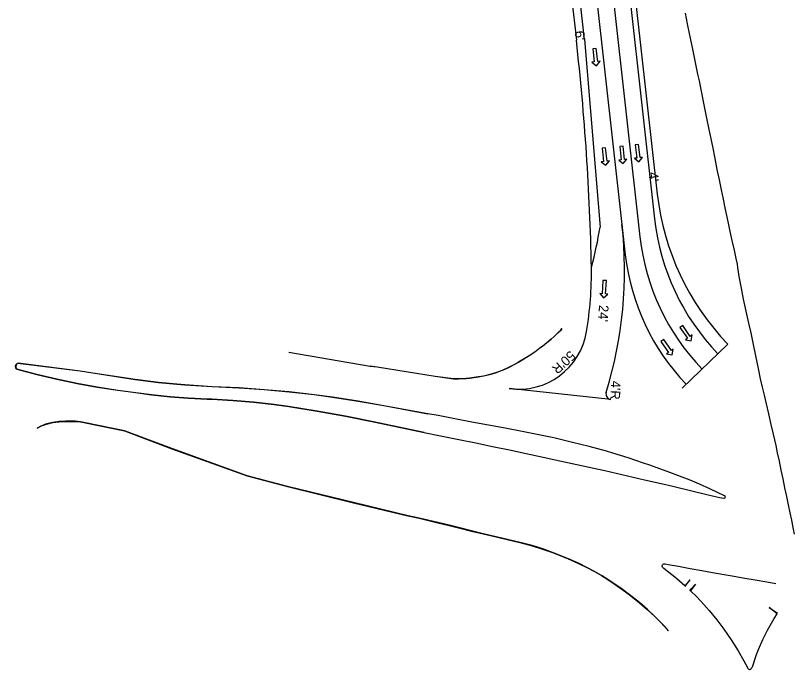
# Model space of a CAD drawing. Extents: x -5665 to 1997148, y 4 to 812485.
# Drawn here: x 1965954 to 1966519, y 789596 to 790071 of the extents above; entities that cross this region are included whole.
import ezdxf

# ---------------------------------------------------------------- set-up
doc = ezdxf.new("R2010")
doc.units = 0
for name, color, linetype in [('RD_EX_Conc', 7, 'Continuous'), ('RD_EX_Road', 7, 'Continuous'), ('RD_PD_ALT1_TrvlWay', 7, 'Continuous'), ('RD_PD_Final_LnLine', 7, 'Continuous'), ('RD_PD_PaveShd', 7, 'Continuous'), ('RD_SHT_TX', 7, 'Continuous')]:
    doc.layers.add(name, color=color, linetype=linetype)

msp = doc.modelspace()

# ---------------------------------------------------------------- linework, layer by layer
at = {"layer": 'RD_EX_Conc'}
msp.add_line((1966152.04, 789826.6), (1966211.27, 789816.49), dxfattribs=at)
for points in [[(1966335.83, 789830.34), (1966340.6, 789834.36), (1966342.72, 789836.11), (1966344.88, 789838.04), (1966348.33, 789841.41), (1966349.66, 789842.67), (1966350.56, 789843.7), (1966349.69, 789842.6), (1966344.95, 789837.97), (1966342.79, 789836.03), (1966336.32, 789830.73), (1966335.83, 789830.34), (1966330.76, 789826.57), (1966326.87, 789823.99), (1966324.42, 789822.5), (1966319, 789819.2), (1966317.35, 789818.26), (1966312.13, 789815.52), (1966307.89, 789813.61), (1966303.01, 789811.75), (1966299.07, 789810.56), (1966293.66, 789809.24), (1966289.86, 789808.56), (1966283.5, 789807.66), (1966280.9, 789807.4), (1966275.5, 789807.12), (1966271.82, 789807.15), (1966258.37, 789809), (1966216.2, 789815.73), (1966211.27, 789816.49), (1966216.21, 789815.83), (1966258.38, 789809.09), (1966271.83, 789807.25), (1966275.5, 789807.22), (1966280.89, 789807.5), (1966283.49, 789807.76), (1966289.84, 789808.65), (1966293.63, 789809.34), (1966299.04, 789810.65), (1966302.97, 789811.85), (1966307.85, 789813.7), (1966312.09, 789815.61), (1966317.3, 789818.35), (1966318.95, 789819.29), (1966326.8, 789824.07), (1966331.91, 789827.43)], [(1966250.48, 789768.18), (1966218.22, 789774.97), (1966213.64, 789775.94), (1966193.16, 789780.04), (1966172.6, 789783.74), (1966151.98, 789787.06), (1966141.38, 789788.49), (1966126.36, 789790.17), (1966111.3, 789791.46), (1966096.22, 789792.36), (1966092.74, 789792.46), (1966079.25, 789793.1), (1966065.78, 789794.13), (1966052.35, 789795.56), (1966038.97, 789797.38), (1966027.74, 789798.85), (1966012.92, 789801.15), (1965998.17, 789803.83), (1965983.49, 789806.9), (1965968.9, 789810.36), (1965954.39, 789814.21), (1965954.21, 789814.38), (1965953.67, 789815.25), (1965953.51, 789816.27), (1965953.76, 789817.28), (1965954.37, 789818.11), (1965955.27, 789818.64), (1966000.56, 789812.96), (1966009.7, 789811.49), (1966040.39, 789806.79), (1966044.33, 789806.22), (1966057.48, 789804.59), (1966070.68, 789803.34), (1966076.62, 789802.87), (1966096.36, 789801.57), (1966116.13, 789800.67), (1966134.17, 789799.44), (1966152.4, 789797.79), (1966170.58, 789795.76), (1966183.89, 789793.94), (1966202.51, 789791.06), (1966221.08, 789787.78), (1966253.16, 789781.91), (1966221.06, 789787.68), (1966202.5, 789790.96), (1966183.87, 789793.84), (1966170.57, 789795.66), (1966152.39, 789797.69), (1966134.16, 789799.34), (1966116.13, 789800.57), (1966096.36, 789801.47), (1966076.61, 789802.77), (1966070.67, 789803.24), (1966057.47, 789804.49), (1966044.31, 789806.13), (1966040.38, 789806.69), (1966009.68, 789811.39), (1966000.54, 789812.86), (1965955.29, 789818.54), (1965954.44, 789818.03), (1965953.85, 789817.23), (1965953.62, 789816.27), (1965953.77, 789815.29), (1965954.29, 789814.44), (1965954.44, 789814.3), (1965968.93, 789810.46), (1965983.52, 789807), (1965998.19, 789803.93), (1966012.94, 789801.24), (1966027.76, 789798.95), (1966038.98, 789797.47), (1966052.36, 789795.66), (1966065.79, 789794.23), (1966079.25, 789793.2), (1966092.74, 789792.56), (1966096.22, 789792.46), (1966111.31, 789791.56), (1966126.37, 789790.27), (1966141.39, 789788.59), (1966152, 789787.16), (1966172.62, 789783.84), (1966193.18, 789780.13), (1966213.66, 789776.04), (1966218.24, 789775.07), (1966250.48, 789768.21), (1966262.3, 789765.84), (1966275.71, 789763.17), (1966287.98, 789760.65), (1966300.19, 789758.08), (1966312.44, 789755.6), (1966324.68, 789752.97), (1966336.92, 789750.39), (1966349.11, 789747.7), (1966361.37, 789745.02), (1966373.65, 789742.27), (1966381.71, 789740.57), (1966398.27, 789736.78), (1966410.5, 789733.99), (1966422.79, 789731.27), (1966431.06, 789729.33), (1966445.89, 789725.53), (1966454.78, 789723.53), (1966461.05, 789722.02), (1966465.4, 789721.1), (1966468.19, 789720.61), (1966468.57, 789720.65), (1966468.94, 789720.71), (1966469.18, 789720.83), (1966469.29, 789721.05), (1966469.34, 789721.35), (1966469.27, 789721.68), (1966469.11, 789722.01), (1966468.94, 789722.18), (1966468.66, 789722.37), (1966463.54, 789724.68), (1966458.02, 789727.22), (1966450.43, 789730.68), (1966443.63, 789733.52), (1966429.06, 789739.16), (1966414.36, 789744.44), (1966409.87, 789745.97), (1966398.72, 789749.83), (1966387.46, 789753.31), (1966383, 789754.57), (1966370.27, 789758.11), (1966358.25, 789761.09), (1966344.69, 789764.32), (1966333.74, 789766.63), (1966321.59, 789768.99), (1966309.35, 789771.32), (1966297.18, 789773.52), (1966284.97, 789775.83), (1966272.8, 789778.17), (1966260.62, 789780.47), (1966253.15, 789781.86)], [(1966421.49, 789631.15), (1966425.46, 789626.99), (1966426.38, 789625.99), (1966428.08, 789624.23), (1966425.53, 789627.06), (1966421.49, 789631.15), (1966417.98, 789634.64), (1966412.63, 789639.73), (1966406.89, 789644.71), (1966399.45, 789650.67), (1966393.38, 789655.14), (1966388.54, 789658.46), (1966383.99, 789661.48), (1966379.29, 789664.41), (1966374.21, 789667.37), (1966368.66, 789670.27), (1966363.02, 789673.07), (1966356.92, 789675.83), (1966350.45, 789678.51), (1966343.68, 789681.1), (1966336.58, 789683.67), (1966328.84, 789686.1), (1966320.09, 789688.35), (1966311.88, 789690.33), (1966302.82, 789692.48), (1966293.28, 789694.76), (1966284.84, 789696.76), (1966276.43, 789698.95), (1966268.56, 789700.87), (1966260.32, 789702.86), (1966246.75, 789706.06), (1966238.7, 789707.74), (1966199.09, 789717.32), (1966151.16, 789729.01), (1966121.76, 789736.88), (1966067.02, 789756.58), (1966032.77, 789769.44), (1966003.1, 789775.62), (1966000.72, 789776.05), (1965996.89, 789776.43), (1965993.04, 789776.4), (1965989.78, 789776.44), (1965985.12, 789776.17), (1965980.51, 789775.5), (1965975.98, 789774.44), (1965972.27, 789773.11), (1965969.16, 789771.5), (1965972.32, 789773.03), (1965976, 789774.34), (1965980.53, 789775.4), (1965985.13, 789776.07), (1965989.78, 789776.34), (1965993.04, 789776.3), (1965996.88, 789776.33), (1966000.7, 789775.96), (1966003.08, 789775.52), (1966032.74, 789769.35), (1966066.98, 789756.48), (1966121.73, 789736.78), (1966151.13, 789728.91), (1966199.06, 789717.22), (1966238.68, 789707.64), (1966246.73, 789705.97), (1966260.3, 789702.76), (1966268.53, 789700.77), (1966276.4, 789698.86), (1966284.82, 789696.67), (1966293.26, 789694.66), (1966302.8, 789692.38), (1966311.85, 789690.23), (1966320.07, 789688.25), (1966328.81, 789686), (1966336.54, 789683.57), (1966343.65, 789681), (1966350.42, 789678.41), (1966356.88, 789675.73), (1966362.98, 789672.98), (1966368.62, 789670.18), (1966374.16, 789667.28), (1966379.24, 789664.33), (1966383.94, 789661.4), (1966388.48, 789658.38), (1966393.32, 789655.06), (1966399.39, 789650.59), (1966406.82, 789644.63), (1966412.56, 789639.66), (1966417.98, 789634.64)], [(1966440.02, 789656.49), (1966440.84, 789657.51), (1966443.84, 789661.29), (1966439.77, 789656.85), (1966434, 789661.98), (1966432.68, 789663.09), (1966430.45, 789664.89), (1966424.58, 789669.57), (1966424.01, 789670.07), (1966423.65, 789670.57), (1966423.5, 789671.13), (1966423.44, 789671.62), (1966423.57, 789672.06), (1966424.17, 789672.67), (1966424.7, 789672.78), (1966425.46, 789672.82), (1966427.88, 789672.42), (1966435.28, 789671.09), (1966443.81, 789669.55), (1966452.13, 789668.09), (1966459.97, 789666.7), (1966474.35, 789664.15), (1966483.39, 789662.54), (1966490.9, 789661.24), (1966499.49, 789659.71), (1966506.04, 789658.58)], [(1966443.58, 789653.38), (1966444.53, 789654.65), (1966447.56, 789658), (1966443.91, 789653.21), (1966448.56, 789648.83), (1966453.71, 789643.45), (1966457.59, 789639.05), (1966463.06, 789632.33), (1966468.22, 789625.38), (1966473.55, 789617.63), (1966478.55, 789609.66), (1966482.75, 789602.32), (1966485.58, 789597.14), (1966485.97, 789596.64), (1966486.45, 789596.31), (1966486.81, 789596.22), (1966487.18, 789596.2), (1966487.56, 789596.3), (1966487.87, 789596.48), (1966488.14, 789596.77), (1966488.39, 789597.08), (1966488.62, 789597.51), (1966488.93, 789598.17), (1966492.01, 789607.01), (1966493.39, 789610.6), (1966496.56, 789617.97), (1966499.87, 789624.74), (1966504.73, 789633.22), (1966506.88, 789636.68), (1966506.88, 789636.68), (1966501.26, 789641.1), (1966507.18, 789636.98)]]:
    msp.add_lwpolyline(points, dxfattribs=at)
at = {"layer": 'RD_EX_Road'}
msp.add_lwpolyline([(1966440.02, 790072.73), (1966441.58, 790065.11), (1966443.29, 790056.75), (1966445.13, 790047.77), (1966447.09, 790038.24), (1966449.13, 790028.48), (1966450.18, 790023.53), (1966451.23, 790018.57), (1966452.26, 790013.62), (1966453.27, 790008.67), (1966454.27, 790003.74), (1966456.21, 789994.07), (1966458.09, 789984.78), (1966459.89, 789975.86), (1966461.6, 789967.3), (1966463.24, 789959.19), (1966464.83, 789951.6), (1966466.34, 789944.45), (1966467.75, 789937.66), (1966469.04, 789931.37), (1966470.19, 789925.75), (1966471.35, 789920.2), (1966472.64, 789914.14), (1966474.07, 789907.6), (1966475.62, 789900.62), (1966476.97, 789894.49), (1966477.81, 789890.48), (1966478.26, 789888), (1966478.46, 789886.46), (1966478.61, 789885.04), (1966478.88, 789882.9), (1966479.51, 789879.18), (1966480.72, 789873.03), (1966482.36, 789865.15), (1966484.29, 789856.28), (1966486.2, 789847.68), (1966487.78, 789840.61), (1966489.35, 789833.3), (1966491.24, 789823.96), (1966493.14, 789814.6), (1966494.73, 789807.22), (1966496.15, 789801.05), (1966497.54, 789795.29), (1966499.02, 789789.13), (1966500.69, 789781.77), (1966502.41, 789774.12), (1966504.03, 789767.08), (1966505.9, 789758.79), (1966507.05, 789753.47), (1966508.35, 789747.38), (1966509.71, 789740.92), (1966511.06, 789734.51), (1966512.37, 789728.14), (1966513.67, 789721.83), (1966514.93, 789715.71), (1966516.14, 789709.92), (1966517.28, 789704.47), (1966518.37, 789699.36), (1966519.44, 789694.33)], dxfattribs=at)
at = {"layer": 'RD_PD_ALT1_TrvlWay'}
for p, q in [((1966367.01, 790053.72), (1966323.13, 790445.02)), ((1966376.88, 790288.69), (1966417.86, 789923.34)), ((1966367.01, 790053.72), (1966378.28, 789917.38)), ((1966394.18, 789919.16), (1966396.63, 789897.3)), ((1966471.11, 789832.4), (1966438.01, 789800.45)), ((1966385.98, 789792.22), (1966312.3, 789800.14))]:
    msp.add_line(p, q, dxfattribs=at)
for centre, radius, start, end in [((1966584.66, 789942.04), 167.85, 186.3991, 223.9944), ((1966091.34, 789963.62), 290.64, 344.9694, 350.8459), ((1966096.05, 789885.73), 300, 342.8673, 6.3991), ((1966556.95, 789915.28), 161.33, 186.3991, 223.9944), ((1966096.05, 789885.73), 276, 350.8191, 0.5225), ((1966319.15, 789849.67), 50, 262.1302, 350.8191), ((1966386.56, 789796.17), 4, 162.8673, 261.7154)]:
    msp.add_arc(centre, radius, start, end, dxfattribs=at)
at = {"layer": 'RD_PD_Final_LnLine'}
for p, q in [((1966335.05, 790446.36), (1966394.18, 789919.16)), ((1966365.1, 790286.08), (1966407.24, 789910.32))]:
    msp.add_line(p, q, dxfattribs=at)
msp.add_arc((1966570.81, 789928.66), 164.59, 186.3991, 223.9944, dxfattribs=at)
at = {"layer": 'RD_PD_PaveShd'}
for p, q in [((1966380.84, 790289.27), (1966419.87, 789941.3)), ((1966351.58, 790137.51), (1966361.05, 790053.05))]:
    msp.add_line(p, q, dxfattribs=at)
for centre, radius, start, end in [((1964541.66, 789849), 1830.8, 1.2283, 6.39908), ((1966605.45, 789962.11), 186.74, 186.3991, 223.9944)]:
    msp.add_arc(centre, radius, start, end, dxfattribs=at)
at = {"layer": 'RD_SHT_TX'}
for points in [[(1966375.51, 790047.15), (1966373.01, 790046.86), (1966374.08, 790037.29), (1966372.38, 790037.1), (1966375.67, 790034.48), (1966378.29, 790037.77), (1966376.59, 790037.58)], [(1966406.32, 789977.38), (1966403.82, 789977.1), (1966404.89, 789967.53), (1966403.19, 789967.34), (1966406.48, 789964.72), (1966409.1, 789968), (1966407.4, 789967.81)], [(1966382.26, 789974.93), (1966379.76, 789974.64), (1966380.83, 789965.07), (1966379.13, 789964.88), (1966382.42, 789962.26), (1966385.04, 789965.55), (1966383.34, 789965.36)], [(1966395.02, 789976.15), (1966392.52, 789975.87), (1966393.59, 789966.3), (1966391.89, 789966.11), (1966395.17, 789963.49), (1966397.79, 789966.77), (1966396.09, 789966.58)], [(1966382.91, 789878.51), (1966380.39, 789878.66), (1966379.81, 789869.05), (1966378.1, 789869.15), (1966380.88, 789866.01), (1966384.03, 789868.79), (1966382.32, 789868.89)], [(1966438.32, 789845.95), (1966436.26, 789844.5), (1966441.79, 789836.62), (1966440.39, 789835.64), (1966444.53, 789834.91), (1966445.25, 789839.05), (1966443.85, 789838.07)], [(1966424.53, 789835.74), (1966422.47, 789834.29), (1966428, 789826.41), (1966426.61, 789825.42), (1966430.74, 789824.7), (1966431.47, 789828.84), (1966430.07, 789827.85)]]:
    msp.add_lwpolyline(points, close=True, dxfattribs=at)

# ---------------------------------------------------------------- texts
for s, rotation, p in [("6'", 275.9047, (1966359.84, 790059.59)), ("4'", 275.9047, (1966413.4, 789957.03)), ("24'", 267.5787, (1966377.49, 789860.94)), ("50'R", 222.6672, (1966356.49, 789828.11)), ("4'R", 267.7921, (1966386.26, 789805.95))]:
    msp.add_text(s, height=7, rotation=rotation, dxfattribs=at).set_placement(p)

doc.saveas('drawing.dxf')
